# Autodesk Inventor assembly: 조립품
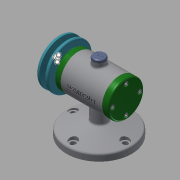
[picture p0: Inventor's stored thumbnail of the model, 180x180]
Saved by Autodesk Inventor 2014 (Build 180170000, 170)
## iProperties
Created: 2018-12
Part Number: 조립품
Document SubType Name: Assembly
Designer: kh
Author: kh
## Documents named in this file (15)
- D:\481207V1028\조립품.iam
- D:\481207V1028\Part1.ipt
- D:\481207V1028\V벨트풀리.ipt
- D:\481207V1028\고무캡.ipt
- D:\481207V1028\너트 M8.ipt
- 너트 M8.ipt
- D:\481207V1028\뒤커버.ipt
- D:\481207V1028\베어링 15 x 32 x 9.ipt
- D:\481207V1028\볼트 M4 x 12.ipt
- D:\481207V1028\스프링와셔 8.ipt
- D:\481207V1028\앞커버.ipt
- D:\481207V1028\오일 실 15 25 7.ipt
- D:\481207V1028\와셔 8x17.ipt
- D:\481207V1028\축.ipt
- D:\481207V1028\키 3 x 3 x 12.ipt
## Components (3 placed, 3 different names)
1. Part1:1 — Insert:1, Insert:2, Angle:3, Insert:14, Insert:15, Insert:19
2. V벨트풀리:1 — Insert:8, Mate:1, Insert:9
3. 고무캡:1 — Angle:3, Angle:4, Angle:5, Insert:19
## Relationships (11: Insert 7, Angle 3, Mate 1)
- Insert:1: Part1:1
- Insert:2: Part1:1
- Insert:8: V벨트풀리:1
- Mate:1: V벨트풀리:1
- Insert:9: V벨트풀리:1
- Angle:3: Part1:1 ↔ 고무캡:1
- Insert:14: Part1:1
- Insert:15: Part1:1
- Angle:4: 고무캡:1
- Angle:5: 고무캡:1
- Insert:19: Part1:1 ↔ 고무캡:1
